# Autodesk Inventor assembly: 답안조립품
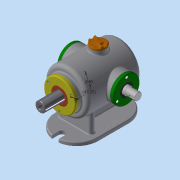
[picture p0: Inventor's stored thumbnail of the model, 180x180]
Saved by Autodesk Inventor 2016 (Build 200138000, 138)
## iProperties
Created: 2018-02
Part Number: 답안조립품
Material: 일반
Document SubType Name: Assembly
Designer: 605-07
Mass: 7551.87 g
Surface Area: 3901.7 cm^2
Volume: 1791.92 cm^3
Density: 4.21439 g/cm^3
Author: 605-07
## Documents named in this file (16)
- C:\Users\605-07\Desktop\380207V1006\답안조립품.iam
- C:\Users\605-07\Desktop\380207V1006\본체.ipt
- C:\Users\605-07\Desktop\380207V1006\베어링 6205.ipt
- 베어링 6205.ipt
- C:\Users\605-07\Desktop\380207V1006\본체커버.ipt
- C:\Users\605-07\Desktop\380207V1006\축 커버-1.ipt
- C:\Users\605-07\Desktop\380207V1006\축 커버-2.ipt
- C:\Users\605-07\Desktop\380207V1006\볼트 M4.ipt
- C:\Users\605-07\Desktop\380207V1006\오일실.ipt
- 오일실.ipt
- C:\Users\605-07\Desktop\380207V1006\부시.ipt
- C:\Users\605-07\Desktop\380207V1006\상부 캡.ipt
- C:\Users\605-07\Desktop\380207V1006\슬라이드 커버.ipt
- C:\Users\605-07\Desktop\380207V1006\슬라이드.ipt
- C:\Users\605-07\Desktop\380207V1006\편심축.ipt
- C:\Users\605-07\Desktop\380207V1006\가변스프링.ipt
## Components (1 placed, 1 different names)
1. 가변스프링:1
